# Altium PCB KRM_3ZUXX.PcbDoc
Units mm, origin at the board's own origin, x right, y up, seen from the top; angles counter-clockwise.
Board outline 60 x 80 mm, 2 copper layers (Top Layer, Bottom Layer); 8 components, 0 nets, 696 pads, 0 vias.
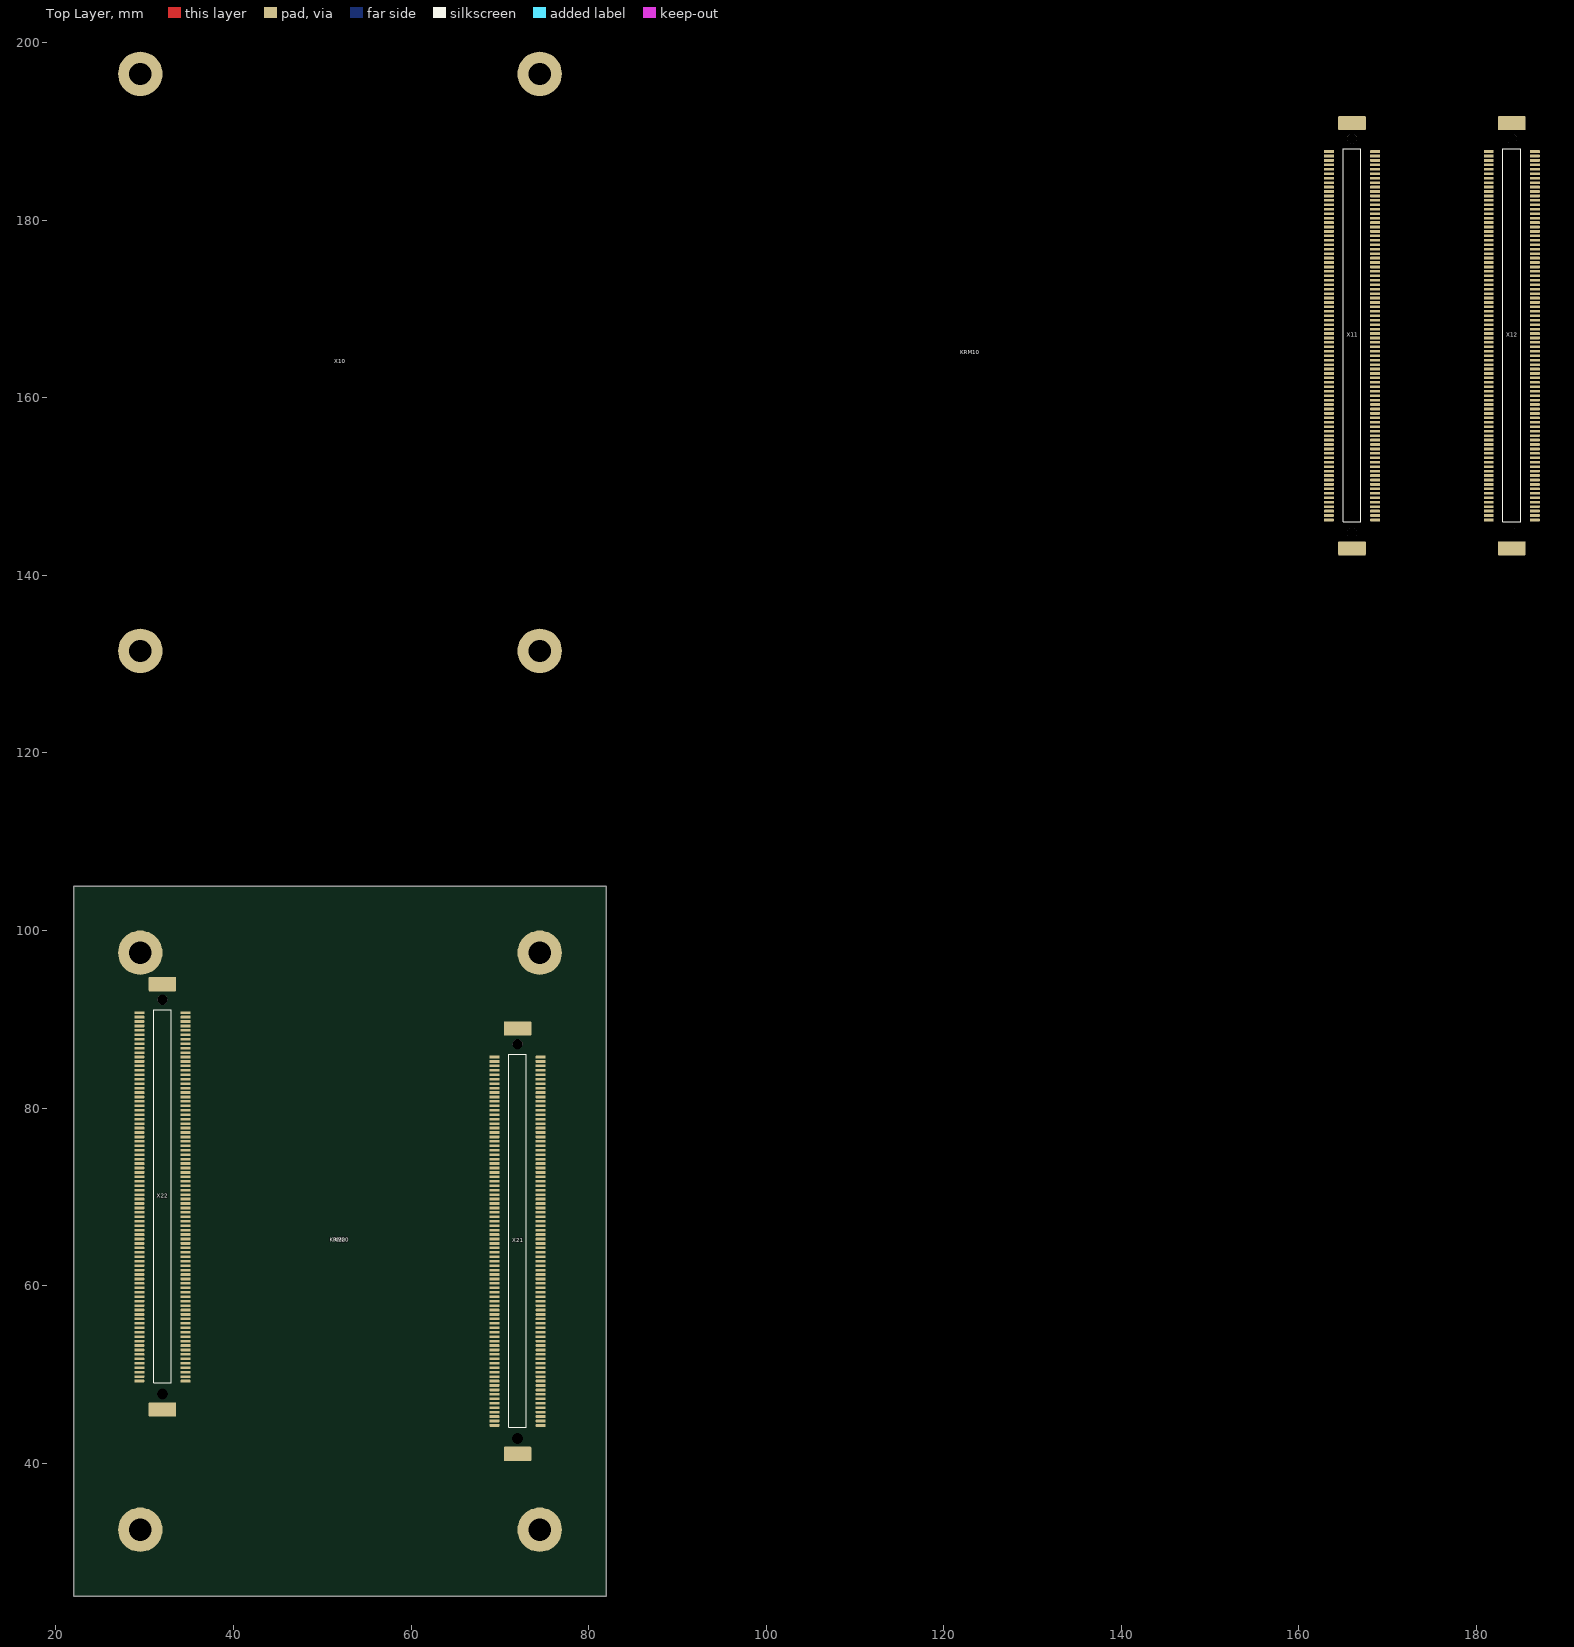
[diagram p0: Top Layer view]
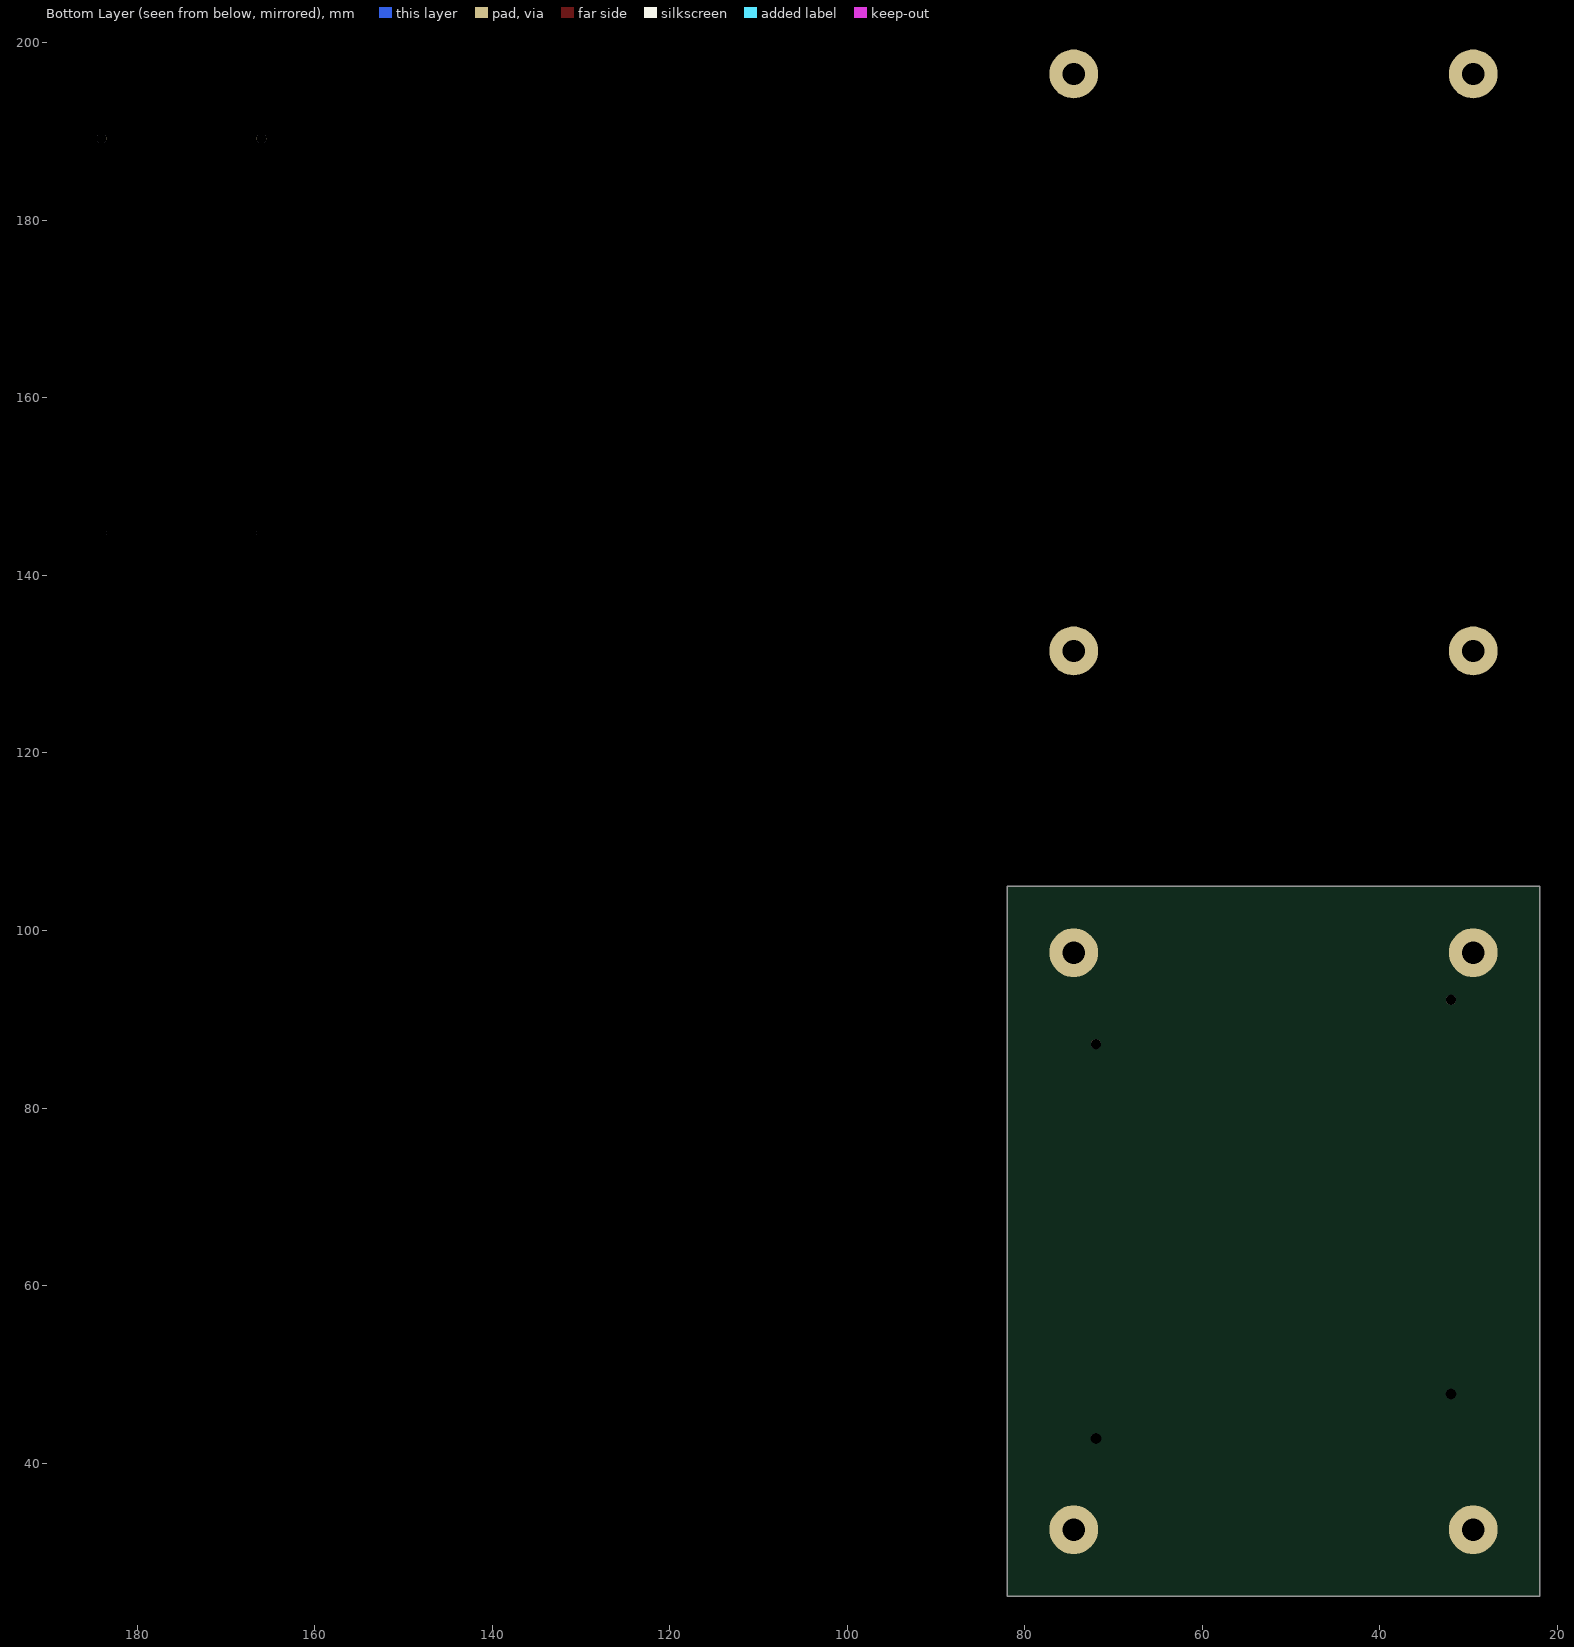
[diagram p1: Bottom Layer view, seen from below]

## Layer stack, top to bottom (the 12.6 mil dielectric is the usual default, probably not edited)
Top Solder: solder mask 0.0102, Solder Resist, Dk 3.5
Top Layer: signal copper 0.0356
Dielectric 1: dielectric 0.32, FR-4, Dk 4.8
Bottom Layer: signal copper 0.0356
Bottom Solder: solder mask 0.0102, Solder Resist, Dk 3.5

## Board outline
22,25 22,105 82,105 82,25

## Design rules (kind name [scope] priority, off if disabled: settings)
Clearance [All] p1: gap=0.254 ignorepadtopadclearanceinfootprint=FALSE except(0: Arc-Hole Track-Hole SMDPad-Hole THPad-Hole Via-Hole Fill-Hole Poly-Hole Region-Hole Text-Hole)
ComponentClearance [All] p1 off: gap=0.254 collisioncheckmode=3 verticalgap=0.254 showdistances=FALSE
PolygonConnect [All] p1: connectstyle=Relief reliefconductorwidth=0.254 reliefentries=4 polygonreliefangle="90 Angle" airgapwidth=0.254
RoutingVias [All] p1: holewidth=0.711 width=1.27 viastyle="Through Hole" minholewidth=0.711 minwidth=1.27 maxholewidth=0.711 maxwidth=1.27
SilkToSilkClearance [All] p1 off: silktosilkclearance=0.254
SolderMaskExpansion [All] p1: expansion=0.102
Width [All] p1: maxlimit=0.254 minlimit=0.254 preferedwidth=0.254
28 further rules are at their usual default settings.

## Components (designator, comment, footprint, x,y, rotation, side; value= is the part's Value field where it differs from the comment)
KRM10 "KRM_3ZUxx_REV_D" KRM_3ZUXX_REV_D 123,165 r90 top
KRM20 "KRM_3ZUxx_REV_D" KRM_3ZUXX_REV_D 52,65 r90 top
X10 "KRM_3A_GENERIC_REV_E" KRM_3A_GENERIC 52,164 r90 top
X11 "X_FX10A-168P-SV1(71)" X_FX10A-168P-SV1(71) 166,167 r0 top
X12 "X_FX10A-168P-SV1(71)" X_FX10A-168P-SV1(71) 184,167 r0 top
X20 "KRM_3A_GENERIC_REV_E" KRM_3A_GENERIC 52,65 r90 top
X21 "X_FX10A-168P-SV1(71)" X_FX10A-168P-SV1(71) 72,65 r0 top
X22 "X_FX10A-168P-SV1(71)" X_FX10A-168P-SV1(71) 32,70 r0 top

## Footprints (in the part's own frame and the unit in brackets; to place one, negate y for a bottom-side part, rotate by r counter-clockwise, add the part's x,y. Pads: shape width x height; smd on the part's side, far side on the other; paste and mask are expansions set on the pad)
KRM_3A_GENERIC [mm] "KR3000 series Module"
  round 5 / inner round 5 / far side round 5.5 hole 2.5: X1(-32.5,-22.5) X2(32.5,-22.5) X3(-32.5,22.5) X4(32.5,22.5)
KRM_3ZUXX_REV_D [mm] "KR3000 series Module ZYNQ ZUxx VERSION_D"
  body extent -35,-25 35,25, height 9.92
X_FX10A-168P-SV1(71) [mm]
  rrect12% 1.1x0.3 smd paste-0.025: 1(-2.6,20.75) 2(2.6,20.75) 3(-2.6,20.25) 4(2.6,20.25) 5(-2.6,19.75) 6(2.6,19.75) 7(-2.6,19.25) 8(2.6,19.25) 9(-2.6,18.75) 10(2.6,18.75) 11(-2.6,18.25) 12(2.6,18.25) 13(-2.6,17.75) 14(2.6,17.75) 15(-2.6,17.25) 16(2.6,17.25) 17(-2.6,16.75) 18(2.6,16.75) 19(-2.6,16.25) 20(2.6,16.25) 21(-2.6,15.75) 22(2.6,15.75) 23(-2.6,15.25) 24(2.6,15.25) 25(-2.6,14.75) 26(2.6,14.75) 27(-2.6,14.25) 28(2.6,14.25) 29(-2.6,13.75) 30(2.6,13.75) 31(-2.6,13.25) 32(2.6,13.25) 33(-2.6,12.75) 34(2.6,12.75) 35(-2.6,12.25) 36(2.6,12.25) 37(-2.6,11.75) 38(2.6,11.75) 39(-2.6,11.25) 40(2.6,11.25) 41(-2.6,10.75) 42(2.6,10.75) 43(-2.6,10.25) 44(2.6,10.25) 45(-2.6,9.75) 46(2.6,9.75) 47(-2.6,9.25) 48(2.6,9.25) 49(-2.6,8.75) 50(2.6,8.75) 51(-2.6,8.25) 52(2.6,8.25) 53(-2.6,7.75) 54(2.6,7.75) 55(-2.6,7.25) 56(2.6,7.25) 57(-2.6,6.75) 58(2.6,6.75) 59(-2.6,6.25) 60(2.6,6.25) 61(-2.6,5.75) 62(2.6,5.75) 63(-2.6,5.25) 64(2.6,5.25) 65(-2.6,4.75) 66(2.6,4.75) 67(-2.6,4.25) 68(2.6,4.25) 69(-2.6,3.75) 70(2.6,3.75) 71(-2.6,3.25) 72(2.6,3.25) 73(-2.6,2.75) 74(2.6,2.75) 75(-2.6,2.25) 76(2.6,2.25) 77(-2.6,1.75) 78(2.6,1.75) 79(-2.6,1.25) 80(2.6,1.25) 81(-2.6,0.75) 82(2.6,0.75) 83(-2.6,0.25) 84(2.6,0.25) 85(-2.6,-0.25) 86(2.6,-0.25) 87(-2.6,-0.75) 88(2.6,-0.75) 89(-2.6,-1.25) 90(2.6,-1.25) 91(-2.6,-1.75) 92(2.6,-1.75) 93(-2.6,-2.25) 94(2.6,-2.25) 95(-2.6,-2.75) 96(2.6,-2.75) 97(-2.6,-3.25) 98(2.6,-3.25) 99(-2.6,-3.75) 100(2.6,-3.75) 101(-2.6,-4.25) 102(2.6,-4.25) 103(-2.6,-4.75) 104(2.6,-4.75)
  rrect25% 1.1x0.3 smd: 105(-2.6,-5.25) 106(2.6,-5.25) 107(-2.6,-5.75) 108(2.6,-5.75) 109(-2.6,-6.25) 110(2.6,-6.25) 111(-2.6,-6.75) 112(2.6,-6.75) 113(-2.6,-7.25) 114(2.6,-7.25) 115(-2.6,-7.75) 116(2.6,-7.75) 117(-2.6,-8.25) 118(2.6,-8.25) 119(-2.6,-8.75) 120(2.6,-8.75) 121(-2.6,-9.25) 122(2.6,-9.25) 123(-2.6,-9.75) 124(2.6,-9.75) 125(-2.6,-10.25) 126(2.6,-10.25) 127(-2.6,-10.75) 128(2.6,-10.75) 129(-2.6,-11.25) 130(2.6,-11.25) 131(-2.6,-11.75) 132(2.6,-11.75) 133(-2.6,-12.25) 134(2.6,-12.25) 135(-2.6,-12.75) 136(2.6,-12.75) 137(-2.6,-13.25) 138(2.6,-13.25) 139(-2.6,-13.75) 140(2.6,-13.75) 141(-2.6,-14.25) 142(2.6,-14.25) 143(-2.6,-14.75) 144(2.6,-14.75) 145(-2.6,-15.25) 146(2.6,-15.25) 147(-2.6,-15.75) 148(2.6,-15.75) 149(-2.6,-16.25) 150(2.6,-16.25) 151(-2.6,-16.75) 152(2.6,-16.75) 153(-2.6,-17.25) 154(2.6,-17.25) 155(-2.6,-17.75) 156(2.6,-17.75) 157(-2.6,-18.25) 158(2.6,-18.25) 159(-2.6,-18.75) 160(2.6,-18.75) 161(-2.6,-19.25) 162(2.6,-19.25) 163(-2.6,-19.75) 164(2.6,-19.75) 165(-2.6,-20.25) 166(2.6,-20.25) 167(-2.6,-20.75) 168(2.6,-20.75)
  rrect12% 3.1x1.6 smd: MP1(0,23.95) MP2(0,-23.95)
  round 1.1 hole 1.15 unplated: X1(0,22.2)
  round 1.1 hole 1.25 unplated: X2(0,-22.2)
  silkscreen extent -1,-20.95 1,21.05, body extent -2.94,-24.55 2.96,24.55, height 4.51

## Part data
KRM10 KRM20: "COM/FPGA MODULE with 3ZUxx FPGAs"
X10 X20: "168 PIN HEADER ASSIGNMENT"
X11 X12 X21 X22: "168 PIN HEADER"

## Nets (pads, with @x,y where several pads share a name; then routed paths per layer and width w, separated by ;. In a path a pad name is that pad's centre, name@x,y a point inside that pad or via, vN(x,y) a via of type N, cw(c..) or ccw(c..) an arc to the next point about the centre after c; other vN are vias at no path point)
pads on no net: X10.X1 X10.X2 X10.X3 X10.X4 X11.1 X11.2 X11.3 X11.4 X11.5 X11.6 X11.7 X11.8 X11.9 X11.10 X11.11 X11.12 X11.13 X11.14 X11.15 X11.16 X11.17 X11.18 X11.19 X11.20 X11.21 X11.22 X11.23 X11.24 X11.25 X11.26 X11.27 X11.28 X11.29 X11.30 X11.31 X11.32 X11.33 X11.34 X11.35 X11.36 X11.37 X11.38 X11.39 X11.40 X11.41 X11.42 X11.43 X11.44 X11.45 X11.46 X11.47 X11.48 X11.49 X11.50 X11.51 X11.52 X11.53 X11.54 X11.55 X11.56 X11.57 X11.58 X11.59 X11.60 X11.61 X11.62 X11.63 X11.64 X11.65 X11.66 X11.67 X11.68 X11.69 X11.70 X11.71 X11.72 X11.73 X11.74 X11.75 X11.76 X11.77 X11.78 X11.79 X11.80 X11.81 X11.82 X11.83 X11.84 X11.85 X11.86 X11.87 X11.88 X11.89 X11.90 X11.91 X11.92 X11.93 X11.94 X11.95 X11.96 X11.97 X11.98 X11.99 X11.100 X11.101 X11.102 X11.103 X11.104 X11.105 X11.106 X11.107 X11.108 X11.109 X11.110 X11.111 X11.112 X11.113 X11.114 X11.115 X11.116 X11.117 X11.118 X11.119 X11.120 X11.121 X11.122 X11.123 X11.124 X11.125 X11.126 X11.127 X11.128 X11.129 X11.130 X11.131 X11.132 X11.133 X11.134 X11.135 X11.136 X11.137 X11.138 X11.139 X11.140 X11.141 X11.142 X11.143 X11.144 X11.145 X11.146 X11.147 X11.148 X11.149 X11.150 X11.151 X11.152 X11.153 X11.154 X11.155 X11.156 X11.157 X11.158 X11.159 X11.160 X11.161 X11.162 X11.163 X11.164 X11.165 X11.166 X11.167 X11.168 X11.MP1 X11.MP2 X11.X1 X11.X2 X12.1 X12.2 X12.3 X12.4 X12.5 X12.6 X12.7 X12.8 X12.9 X12.10 X12.11 X12.12 X12.13 X12.14 X12.15 X12.16 X12.17 X12.18 X12.19 X12.20 X12.21 X12.22 X12.23 X12.24 X12.25 X12.26 X12.27 X12.28 X12.29 X12.30 X12.31 X12.32 X12.33 X12.34 X12.35 X12.36 X12.37 X12.38 X12.39 X12.40 X12.41 X12.42 X12.43 X12.44 X12.45 X12.46 X12.47 X12.48 X12.49 X12.50 X12.51 X12.52 X12.53 X12.54 X12.55 X12.56 X12.57 X12.58 X12.59 X12.60 X12.61 X12.62 X12.63 X12.64 X12.65 X12.66 X12.67 X12.68 X12.69 X12.70 X12.71 X12.72 X12.73 X12.74 X12.75 X12.76 X12.77 X12.78 X12.79 X12.80 X12.81 X12.82 X12.83 X12.84 X12.85 X12.86 X12.87 X12.88 X12.89 X12.90 X12.91 X12.92 X12.93 X12.94 X12.95 X12.96 X12.97 X12.98 X12.99 X12.100 X12.101 X12.102 X12.103 X12.104 X12.105 X12.106 X12.107 X12.108 X12.109 X12.110 X12.111 X12.112 X12.113 X12.114 X12.115 X12.116 X12.117 X12.118 X12.119 X12.120 X12.121 X12.122 X12.123 X12.124 X12.125 X12.126 X12.127 X12.128 X12.129 X12.130 X12.131 X12.132 X12.133 X12.134 X12.135 X12.136 X12.137 X12.138 X12.139 X12.140 X12.141 X12.142 X12.143 X12.144 X12.145 X12.146 X12.147 X12.148 X12.149 X12.150 X12.151 X12.152 X12.153 X12.154 X12.155 X12.156 X12.157 X12.158 X12.159 X12.160 X12.161 X12.162 X12.163 X12.164 X12.165 X12.166 X12.167 X12.168 X12.MP1 X12.MP2 X12.X1 X12.X2 X20.X1 X20.X2 X20.X3 X20.X4 X21.1 X21.2 X21.3 X21.4 X21.5 X21.6 X21.7 X21.8 X21.9 X21.10 X21.11 X21.12 X21.13 X21.14 X21.15 X21.16 X21.17 X21.18 X21.19 X21.20 X21.21 X21.22 X21.23 X21.24 X21.25 X21.26 X21.27 X21.28 X21.29 X21.30 X21.31 X21.32 X21.33 X21.34 X21.35 X21.36 X21.37 X21.38 X21.39 X21.40 X21.41 X21.42 X21.43 X21.44 X21.45 X21.46 X21.47 X21.48 X21.49 X21.50 X21.51 X21.52 X21.53 X21.54 X21.55 X21.56 X21.57 X21.58 X21.59 X21.60 X21.61 X21.62 X21.63 X21.64 X21.65 X21.66 X21.67 X21.68 X21.69 X21.70 X21.71 X21.72 X21.73 X21.74 X21.75 X21.76 X21.77 X21.78 X21.79 X21.80 X21.81 X21.82 X21.83 X21.84 X21.85 X21.86 X21.87 X21.88 X21.89 X21.90 X21.91 X21.92 X21.93 X21.94 X21.95 X21.96 X21.97 X21.98 X21.99 X21.100 X21.101 X21.102 X21.103 X21.104 X21.105 X21.106 X21.107 X21.108 X21.109 X21.110 X21.111 X21.112 X21.113 X21.114 X21.115 X21.116 X21.117 X21.118 X21.119 X21.120 X21.121 X21.122 X21.123 X21.124 X21.125 X21.126 X21.127 X21.128 X21.129 X21.130 X21.131 X21.132 X21.133 X21.134 X21.135 X21.136 X21.137 X21.138 X21.139 X21.140 X21.141 X21.142 X21.143 X21.144 X21.145 X21.146 X21.147 X21.148 X21.149 X21.150 X21.151 X21.152 X21.153 X21.154 X21.155 X21.156 X21.157 X21.158 X21.159 X21.160 X21.161 X21.162 X21.163 X21.164 X21.165 X21.166 X21.167 X21.168 X21.MP1 X21.MP2 X21.X1 X21.X2 X22.1 X22.2 X22.3 X22.4 X22.5 X22.6 X22.7 X22.8 X22.9 X22.10 X22.11 X22.12 X22.13 X22.14 X22.15 X22.16 X22.17 X22.18 X22.19 X22.20 X22.21 X22.22 X22.23 X22.24 X22.25 X22.26 X22.27 X22.28 X22.29 X22.30 X22.31 X22.32 X22.33 X22.34 X22.35 X22.36 X22.37 X22.38 X22.39 X22.40 X22.41 X22.42 X22.43 X22.44 X22.45 X22.46 X22.47 X22.48 X22.49 X22.50 X22.51 X22.52 X22.53 X22.54 X22.55 X22.56 X22.57 X22.58 X22.59 X22.60 X22.61 X22.62 X22.63 X22.64 X22.65 X22.66 X22.67 X22.68 X22.69 X22.70 X22.71 X22.72 X22.73 X22.74 X22.75 X22.76 X22.77 X22.78 X22.79 X22.80 X22.81 X22.82 X22.83 X22.84 X22.85 X22.86 X22.87 X22.88 X22.89 X22.90 X22.91 X22.92 X22.93 X22.94 X22.95 X22.96 X22.97 X22.98 X22.99 X22.100 X22.101 X22.102 X22.103 X22.104 X22.105 X22.106 X22.107 X22.108 X22.109 X22.110 X22.111 X22.112 X22.113 X22.114 X22.115 X22.116 X22.117 X22.118 X22.119 X22.120 X22.121 X22.122 X22.123 X22.124 X22.125 X22.126 X22.127 X22.128 X22.129 X22.130 X22.131 X22.132 X22.133 X22.134 X22.135 X22.136 X22.137 X22.138 X22.139 X22.140 X22.141 X22.142 X22.143 X22.144 X22.145 X22.146 X22.147 X22.148 X22.149 X22.150 X22.151 X22.152 X22.153 X22.154 X22.155 X22.156 X22.157 X22.158 X22.159 X22.160 X22.161 X22.162 X22.163 X22.164 X22.165 X22.166 X22.167 X22.168 X22.MP1 X22.MP2 X22.X1 X22.X2

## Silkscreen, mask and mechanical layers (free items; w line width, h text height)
Mechanical 1:
  the board outline again, w0.2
